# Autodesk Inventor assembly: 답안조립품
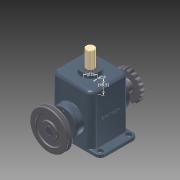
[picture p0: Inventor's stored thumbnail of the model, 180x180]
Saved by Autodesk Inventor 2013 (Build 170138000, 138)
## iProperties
Created: 2015-01
Part Number: 답안조립품
Document SubType Name: Assembly
Designer: user11
Mass: 8618.01 g
Surface Area: 4423.81 cm^2
Volume: 1987.46 cm^3
Density: 4.3362 g/cm^3
Author: user11
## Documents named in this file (15)
- C:\Users\User11\Desktop\350105V1022\답안조립품.iam
- C:\Users\User11\Desktop\350105V1022\본체.ipt
- C:\Users\User11\Desktop\350105V1022\부시.ipt
- C:\Users\User11\Desktop\350105V1022\베어링 6205.ipt
- C:\Users\User11\Desktop\350105V1022\커버.ipt
- C:\Users\User11\Desktop\350105V1022\M4x0.5.ipt
- C:\Users\User11\Desktop\350105V1022\편심축.ipt
- C:\Users\User11\Desktop\350105V1022\키 8x8.ipt
- C:\Users\User11\Desktop\350105V1022\멈춤링.ipt
- C:\Users\User11\Desktop\350105V1022\오일실.ipt
- C:\Users\User11\Desktop\350105V1022\V-벨트풀리.ipt
- C:\Users\User11\Desktop\350105V1022\멈춤나사 M5x0.5.ipt
- C:\Users\User11\Desktop\350105V1022\체인 스프로킷.ipt
- C:\Users\User11\Desktop\350105V1022\슬라이드.ipt
- C:\Users\User11\Desktop\350105V1022\스프링.ipt
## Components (8 placed, 3 different names)
1. V-벨트풀리:1 — 플러쉬:1, 각도:1
2. 5-체인 스프로킷:1 — 플러쉬:2
3. M4x0.5:1
4. M4x0.5:3
5. M4x0.5:4
6. M4x0.5:2
7. M4x0.5:5
8. M4x0.5:6
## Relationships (3: Flush 2, Angle 1)
- 플러쉬:1 [Flush]: V-벨트풀리:1
- 플러쉬:2 [Flush]: 5-체인 스프로킷:1
- 각도:1 [Angle]: V-벨트풀리:1
